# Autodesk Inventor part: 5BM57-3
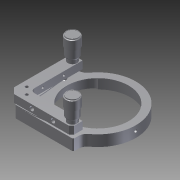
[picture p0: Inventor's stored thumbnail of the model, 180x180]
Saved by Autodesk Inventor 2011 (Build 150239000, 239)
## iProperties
Created: 2011-06
Part Number: 5BM57-3
Document SubType Name: Modeling
Designer: vadybininkas6
Density: 1 g/cm^3
Author: vadybininkas6
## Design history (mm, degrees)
feature "Base1"
body "Solid1"
